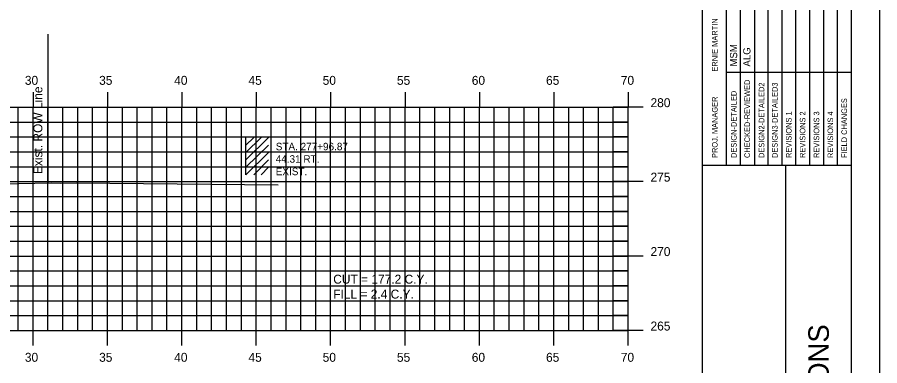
# Model space of a CAD drawing. Extents: x 854453 to 854623, y 366268 to 366378.
# Drawn here: x 854565.4 to 854623.3, y 366302.8 to 366326.2 of the extents above; entities that cross this region are included whole.
import ezdxf

# ---------------------------------------------------------------- set-up
doc = ezdxf.new("R2010")
doc.units = 0
for name, color, linetype in [('ANNOTATION', 7, 'Continuous'), ('BORDER', 7, 'Continuous'), ('D_Text_Monospaced', 7, 'Continuous'), ('E_ROW_Line', 7, 'Continuous'), ('H_V ANNOTATION', 7, 'Continuous'), ('MAJOR', 7, 'Continuous'), ('MINOR', 7, 'Continuous'), ('PLOT BOUNDARY', 7, 'Continuous'), ('S_Buildings_SillElevation', 7, 'Continuous'), ('S_Roadway_Centerline', 7, 'Continuous')]:
    doc.layers.add(name, color=color, linetype=linetype)

msp = doc.modelspace()

# ---------------------------------------------------------------- linework, layer by layer
at = {"layer": 'BORDER'}
for p, q in [((854611.439, 366271.236), (854611.439, 366376.239)), ((854621.439, 366271.236), (854621.439, 366376.236)), ((854611.439, 366316.239), (854621.439, 366316.239)), ((854617.03, 366281.239), (854617.03, 366316.239))]:
    msp.add_line(p, q, dxfattribs=at)
for points in [[(854613.986, 366316.242), (854613.986, 366333.739)], [(854614.918, 366333.739), (854614.918, 366316.242)], [(854615.85, 366316.242), (854615.85, 366333.739)], [(854616.781, 366316.242), (854616.781, 366333.739)], [(854617.713, 366316.242), (854617.713, 366333.739)], [(854618.645, 366316.242), (854618.645, 366333.739)], [(854619.576, 366316.242), (854619.576, 366333.739)], [(854620.508, 366316.242), (854620.508, 366333.739)], [(854613.055, 366316.242), (854613.055, 366333.033)], [(854613.054, 366322.489), (854621.439, 366322.489)]]:
    msp.add_lwpolyline(points, dxfattribs=at)
at = {"layer": 'E_ROW_Line'}
msp.add_line((854567.461, 366315.045), (854567.461, 366325.045), dxfattribs=at)
at = {"layer": 'MAJOR'}
for p, q in [((854566.439, 366321.143), (854566.439, 366320.141)), ((854571.439, 366321.143), (854571.439, 366320.141)), ((854576.439, 366321.143), (854576.439, 366320.141)), ((854581.439, 366321.143), (854581.439, 366320.141)), ((854586.439, 366321.143), (854586.439, 366320.141)), ((854591.439, 366321.143), (854591.439, 366320.141)), ((854596.439, 366321.143), (854596.439, 366320.141)), ((854601.439, 366321.143), (854601.439, 366320.141)), ((854606.439, 366321.143), (854606.439, 366320.141)), ((854466.439, 366320.141), (854606.439, 366320.141)), ((854466.439, 366320.141), (854606.439, 366320.141)), ((854566.439, 366305.141), (854566.439, 366320.141)), ((854571.439, 366305.141), (854571.439, 366320.141)), ((854576.439, 366305.141), (854576.439, 366320.141)), ((854581.439, 366305.141), (854581.439, 366320.141)), ((854586.439, 366305.141), (854586.439, 366320.141)), ((854591.439, 366305.141), (854591.439, 366320.141)), ((854596.439, 366305.141), (854596.439, 366320.141)), ((854601.439, 366305.141), (854601.439, 366320.141)), ((854607.441, 366320.141), (854605.437, 366320.141)), ((854606.439, 366305.141), (854606.439, 366320.141)), ((854606.439, 366305.141), (854606.439, 366320.141)), ((854466.439, 366315.141), (854606.439, 366315.141)), ((854607.441, 366315.141), (854605.437, 366315.141)), ((854466.439, 366310.141), (854606.439, 366310.141)), ((854607.441, 366310.141), (854605.437, 366310.141)), ((854466.439, 366305.141), (854606.439, 366305.141)), ((854466.439, 366305.141), (854606.439, 366305.141)), ((854566.439, 366304.139), (854566.439, 366305.141)), ((854571.439, 366304.139), (854571.439, 366305.141)), ((854576.439, 366304.139), (854576.439, 366305.141)), ((854581.439, 366304.139), (854581.439, 366305.141)), ((854586.439, 366304.139), (854586.439, 366305.141)), ((854591.439, 366304.139), (854591.439, 366305.141)), ((854596.439, 366304.139), (854596.439, 366305.141)), ((854601.439, 366304.139), (854601.439, 366305.141)), ((854607.441, 366305.141), (854605.437, 366305.141)), ((854606.439, 366304.139), (854606.439, 366305.141))]:
    msp.add_line(p, q, dxfattribs=at)
at = {"layer": 'MINOR'}
for p, q in [((854565.439, 366305.141), (854565.439, 366320.141)), ((854567.439, 366305.141), (854567.439, 366320.141)), ((854568.439, 366305.141), (854568.439, 366320.141)), ((854569.439, 366305.141), (854569.439, 366320.141)), ((854570.439, 366305.141), (854570.439, 366320.141)), ((854572.439, 366305.141), (854572.439, 366320.141)), ((854573.439, 366305.141), (854573.439, 366320.141)), ((854574.439, 366305.141), (854574.439, 366320.141)), ((854575.439, 366305.141), (854575.439, 366320.141)), ((854577.439, 366305.141), (854577.439, 366320.141)), ((854578.439, 366305.141), (854578.439, 366320.141)), ((854579.439, 366305.141), (854579.439, 366320.141)), ((854580.439, 366305.141), (854580.439, 366320.141)), ((854582.439, 366305.141), (854582.439, 366320.141)), ((854583.439, 366305.141), (854583.439, 366320.141)), ((854584.439, 366305.141), (854584.439, 366320.141)), ((854585.439, 366305.141), (854585.439, 366320.141)), ((854587.439, 366305.141), (854587.439, 366320.141)), ((854588.439, 366305.141), (854588.439, 366320.141)), ((854589.439, 366305.141), (854589.439, 366320.141)), ((854590.439, 366305.141), (854590.439, 366320.141)), ((854592.439, 366305.141), (854592.439, 366320.141)), ((854593.439, 366305.141), (854593.439, 366320.141)), ((854594.439, 366305.141), (854594.439, 366320.141)), ((854595.439, 366305.141), (854595.439, 366320.141)), ((854597.439, 366305.141), (854597.439, 366320.141)), ((854598.439, 366305.141), (854598.439, 366320.141)), ((854599.439, 366305.141), (854599.439, 366320.141)), ((854600.439, 366305.141), (854600.439, 366320.141)), ((854602.439, 366305.141), (854602.439, 366320.141)), ((854603.439, 366305.141), (854603.439, 366320.141)), ((854604.439, 366305.141), (854604.439, 366320.141)), ((854605.439, 366305.141), (854605.439, 366320.141)), ((854466.439, 366319.141), (854606.439, 366319.141)), ((854606.439, 366319.141), (854605.437, 366319.141)), ((854466.439, 366318.141), (854606.439, 366318.141)), ((854606.439, 366318.141), (854605.437, 366318.141)), ((854466.439, 366317.141), (854606.439, 366317.141)), ((854606.439, 366317.141), (854605.437, 366317.141)), ((854466.439, 366316.141), (854606.439, 366316.141)), ((854606.439, 366316.141), (854605.437, 366316.141)), ((854466.439, 366314.141), (854606.439, 366314.141)), ((854606.439, 366314.141), (854605.437, 366314.141)), ((854466.439, 366313.141), (854606.439, 366313.141)), ((854606.439, 366313.141), (854605.437, 366313.141)), ((854466.439, 366312.141), (854606.439, 366312.141)), ((854606.439, 366312.141), (854605.437, 366312.141)), ((854466.439, 366311.141), (854606.439, 366311.141)), ((854606.439, 366311.141), (854605.437, 366311.141)), ((854466.439, 366309.141), (854606.439, 366309.141)), ((854606.439, 366309.141), (854605.437, 366309.141)), ((854466.439, 366308.141), (854606.439, 366308.141)), ((854606.439, 366308.141), (854605.437, 366308.141)), ((854466.439, 366307.141), (854606.439, 366307.141)), ((854606.439, 366307.141), (854605.437, 366307.141)), ((854466.439, 366306.141), (854606.439, 366306.141)), ((854606.439, 366306.141), (854605.437, 366306.141))]:
    msp.add_line(p, q, dxfattribs=at)
at = {"layer": 'PLOT BOUNDARY'}
msp.add_lwpolyline([(854453.345, 366268.177), (854623.345, 366268.177), (854623.345, 366378.177), (854453.345, 366378.177)], close=True, dxfattribs=at)
at = {"layer": 'S_Buildings_SillElevation'}
for p, q in [((854580.745, 366315.586), (854580.745, 366318.113)), ((854580.745, 366316.603), (854582.255, 366318.113)), ((854580.745, 366317.095), (854581.762, 366318.113)), ((854580.745, 366317.588), (854581.27, 366318.113)), ((854580.745, 366316.111), (854582.255, 366317.588)), ((854580.745, 366315.586), (854582.255, 366317.095)), ((854581.27, 366315.586), (854582.255, 366316.603)), ((854581.762, 366315.586), (854582.255, 366316.111))]:
    msp.add_line(p, q, dxfattribs=at)
at = {"layer": 'S_Roadway_Centerline'}
msp.add_lwpolyline([(854562.191, 366314.943), (854567.654, 366315.049), (854568.283, 366315.04), (854569.343, 366315.054), (854582.919, 366314.934)], dxfattribs=at)

# ---------------------------------------------------------------- texts
at = {"layer": 'ANNOTATION'}
for s, p in [('CUT = 177.2 C.Y.', (854586.615, 366308.29)), ('FILL = 2.4 C.Y.', (854586.615, 366307.288))]:
    msp.add_text(s, height=0.6, dxfattribs=at).set_placement(p)
at = {"layer": 'BORDER'}
for s, height, p in [('ERNIE MARTIN', 0.37275, (854612.443, 366322.531)), ('MSM', 0.4845, (854613.762, 366322.863)), ('ALG', 0.4845, (854614.656, 366322.863)), ('CHECKED-REVIEWED', 0.37275, (854614.62, 366316.727)), ('DESIGN2-DETAILED2', 0.37275, (854615.589, 366316.727)), ('DESIGN3-DETAILED3', 0.37275, (854616.483, 366316.727)), ('PROJ. MANAGER', 0.37275, (854612.443, 366316.727)), ('DESIGN-DETAILED', 0.37275, (854613.725, 366316.727)), ('FIELD CHANGES', 0.37275, (854621.142, 366316.727)), ('REVISIONS 1', 0.37275, (854617.415, 366316.727)), ('REVISIONS 2', 0.37275, (854618.347, 366316.727)), ('REVISIONS 3', 0.37275, (854619.278, 366316.727)), ('REVISIONS 4', 0.37275, (854620.21, 366316.727)), ('CROSS SECTIONS', 1.37787, (854619.923, 366289.073))]:
    msp.add_text(s, height=height, rotation=90, dxfattribs=at).set_placement(p)
at = {"layer": 'D_Text_Monospaced'}
for s, height, p in [('STA. 277+96.87', 0.49998, (854582.749, 366317.246)), ('44.31 RT.', 0.5, (854582.749, 366316.412)), ('EXIST. ', 0.5, (854582.749, 366315.572))]:
    msp.add_text(s, height=height, dxfattribs=at).set_placement(p)
at = {"layer": 'E_ROW_Line'}
msp.add_text('Exist. ROW Line', height=0.6, rotation=90, dxfattribs=at).set_placement((854567.061, 366315.645))
at = {"layer": 'H_V ANNOTATION'}
for s, p in [('30', (854565.887, 366321.641)), ('35', (854570.879, 366321.641)), ('40', (854575.925, 366321.641)), ('45', (854580.917, 366321.641)), ('50', (854585.903, 366321.641)), ('55', (854590.895, 366321.641)), ('60', (854595.925, 366321.641)), ('65', (854600.917, 366321.641)), ('70', (854605.941, 366321.641)), ('280', (854607.939, 366320.141)), ('275', (854607.939, 366315.141)), ('270', (854607.939, 366310.141)), ('265', (854607.939, 366305.141)), ('30', (854565.887, 366303.041)), ('35', (854570.879, 366303.041)), ('40', (854575.925, 366303.041)), ('45', (854580.917, 366303.041)), ('50', (854585.903, 366303.041)), ('55', (854590.895, 366303.041)), ('60', (854595.925, 366303.041)), ('65', (854600.917, 366303.041)), ('70', (854605.941, 366303.041))]:
    msp.add_text(s, height=0.6, dxfattribs=at).set_placement(p)

doc.saveas('drawing.dxf')
